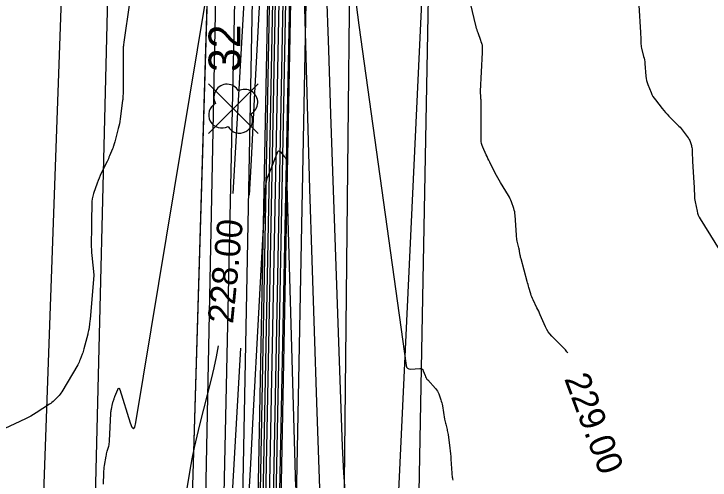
# Model space of a CAD drawing. Extents: x -534410 to -534262, y -1190162 to -1189584.
# Drawn here: x -534375.88 to -534348.61, y -1189725.88 to -1189707.6 of the extents above; entities that cross this region are included whole.
import ezdxf

# ---------------------------------------------------------------- set-up
doc = ezdxf.new("R2010")
doc.units = 0
for name, color, linetype in [('30', 7, 'Continuous'), ('31', 7, 'Continuous'), ('40', 7, 'Continuous'), ('_linie', 7, 'Continuous'), ('_N_osa', 7, 'Continuous'), ('_N_tenká', 7, 'Continuous'), ('_N_tenká_velmi', 7, 'Continuous'), ('_přístup', 7, 'Continuous'), ('_tenka', 7, 'Continuous'), ('Default', 7, 'Continuous'), ('Hranice parcel', 7, 'Continuous')]:
    doc.layers.add(name, color=color, linetype=linetype)

msp = doc.modelspace()

# ---------------------------------------------------------------- linework, layer by layer
at = {"layer": '30'}
for points in [[(-534365.702, -1189685.448), (-534366.553, -1189701.366), (-534366.64, -1189702.98), (-534366.729, -1189704.594), (-534366.819, -1189706.208), (-534366.911, -1189707.822), (-534367.302, -1189714.644)], [(-534362.885, -1189726.642), (-534362.961, -1189725.602), (-534363.011, -1189724.559), (-534363.467, -1189711.528), (-534363.552, -1189709.008), (-534363.634, -1189706.488), (-534363.71, -1189703.968), (-534363.782, -1189701.447), (-534364.144, -1189688.321)], [(-534371.366, -1189707.267), (-534371.561, -1189708.625), (-534371.574, -1189708.713), (-534371.588, -1189708.81), (-534371.59, -1189708.827), (-534371.592, -1189708.845), (-534371.594, -1189708.862), (-534371.595, -1189708.88), (-534371.6, -1189708.95), (-534371.601, -1189708.967), (-534371.602, -1189708.985), (-534371.603, -1189709.003), (-534371.603, -1189709.02), (-534371.603, -1189710.669), (-534371.603, -1189710.686), (-534371.603, -1189710.704), (-534371.604, -1189710.722), (-534371.605, -1189710.739), (-534371.609, -1189710.814), (-534371.611, -1189710.844), (-534371.614, -1189710.875), (-534371.618, -1189710.937), (-534371.619, -1189710.952), (-534371.62, -1189710.968), (-534371.622, -1189710.983), (-534371.624, -1189710.998), (-534371.718, -1189711.722), (-534371.732, -1189711.816), (-534371.749, -1189711.91), (-534371.769, -1189712.003), (-534371.792, -1189712.095), (-534371.934, -1189712.623), (-534371.954, -1189712.697), (-534371.98, -1189712.795), (-534371.987, -1189712.82), (-534371.995, -1189712.844), (-534372.004, -1189712.868), (-534372.013, -1189712.891), (-534372.133, -1189713.172), (-534372.157, -1189713.226), (-534372.181, -1189713.28), (-534372.206, -1189713.334), (-534372.232, -1189713.388), (-534372.457, -1189713.849), (-534372.501, -1189713.944), (-534372.543, -1189714.041), (-534372.582, -1189714.139), (-534372.618, -1189714.238), (-534372.758, -1189714.643), (-534372.788, -1189714.744), (-534372.81, -1189714.847), (-534372.824, -1189714.952), (-534372.83, -1189715.058), (-534372.839, -1189715.699), (-534372.84, -1189715.723), (-534372.84, -1189715.748), (-534372.84, -1189715.772), (-534372.84, -1189715.796), (-534372.84, -1189715.893), (-534372.84, -1189715.917), (-534372.84, -1189715.941), (-534372.84, -1189715.966), (-534372.841, -1189715.99), (-534372.85, -1189716.619), (-534372.85, -1189716.732), (-534372.846, -1189716.844), (-534372.839, -1189716.957), (-534372.829, -1189717.069), (-534372.747, -1189717.839), (-534372.747, -1189717.849), (-534372.747, -1189717.85), (-534372.9, -1189719.581), (-534372.905, -1189719.63), (-534372.91, -1189719.679), (-534372.916, -1189719.727), (-534372.923, -1189719.776), (-534372.952, -1189719.97), (-534372.959, -1189720.019), (-534372.968, -1189720.067), (-534372.979, -1189720.115), (-534372.99, -1189720.162), (-534373.136, -1189720.736), (-534373.151, -1189720.79), (-534373.167, -1189720.844), (-534373.185, -1189720.897), (-534373.204, -1189720.949), (-534373.285, -1189721.158), (-534373.306, -1189721.21), (-534373.329, -1189721.261), (-534373.354, -1189721.311), (-534373.382, -1189721.359), (-534374.008, -1189722.424), (-534374.038, -1189722.472), (-534374.072, -1189722.517), (-534374.107, -1189722.561), (-534374.146, -1189722.602), (-534374.307, -1189722.764), (-534374.348, -1189722.803), (-534374.391, -1189722.84), (-534374.435, -1189722.874), (-534374.482, -1189722.906), (-534375.005, -1189723.243), (-534375.109, -1189723.308), (-534375.215, -1189723.369), (-534375.323, -1189723.427), (-534375.433, -1189723.48), (-534377.082, -1189724.25)], [(-534354.184, -1189720.889), (-534354.22, -1189720.847), (-534354.283, -1189720.779), (-534354.348, -1189720.712), (-534354.818, -1189720.233), (-534354.892, -1189720.151), (-534354.957, -1189720.064), (-534355.013, -1189719.971), (-534355.061, -1189719.872), (-534355.263, -1189719.406), (-534355.295, -1189719.334), (-534355.327, -1189719.263), (-534355.36, -1189719.193), (-534355.394, -1189719.122), (-534355.545, -1189718.817), (-534355.572, -1189718.759), (-534355.596, -1189718.7), (-534355.617, -1189718.641), (-534355.637, -1189718.58), (-534355.708, -1189718.336), (-534355.725, -1189718.275), (-534355.743, -1189718.214), (-534355.76, -1189718.152), (-534355.777, -1189718.091), (-534356.019, -1189717.212), (-534356.028, -1189717.176), (-534356.037, -1189717.14), (-534356.045, -1189717.103), (-534356.052, -1189717.066), (-534356.077, -1189716.918), (-534356.084, -1189716.881), (-534356.091, -1189716.845), (-534356.098, -1189716.808), (-534356.106, -1189716.771), (-534356.166, -1189716.508), (-534356.178, -1189716.452), (-534356.187, -1189716.395), (-534356.194, -1189716.338), (-534356.199, -1189716.281), (-534356.248, -1189715.494), (-534356.255, -1189715.427), (-534356.266, -1189715.36), (-534356.282, -1189715.294), (-534356.302, -1189715.23), (-534356.392, -1189714.973), (-534356.416, -1189714.909), (-534356.443, -1189714.848), (-534356.474, -1189714.787), (-534356.508, -1189714.729), (-534356.822, -1189714.218), (-534356.877, -1189714.126), (-534356.93, -1189714.033), (-534356.981, -1189713.939), (-534357.03, -1189713.844), (-534357.246, -1189713.413), (-534357.282, -1189713.341), (-534357.317, -1189713.269), (-534357.351, -1189713.196), (-534357.384, -1189713.123), (-534357.517, -1189712.83), (-534357.545, -1189712.756), (-534357.566, -1189712.68), (-534357.578, -1189712.603), (-534357.583, -1189712.523), (-534357.583, -1189711.08), (-534357.583, -1189711.042), (-534357.584, -1189711.005), (-534357.586, -1189710.968), (-534357.588, -1189710.93), (-534357.599, -1189710.781), (-534357.602, -1189710.744), (-534357.603, -1189710.706), (-534357.603, -1189710.669), (-534357.602, -1189710.632), (-534357.531, -1189709.112), (-534357.53, -1189709.085), (-534357.529, -1189709.058), (-534357.528, -1189709.032), (-534357.528, -1189709.005), (-534357.525, -1189708.887), (-534357.526, -1189708.866), (-534357.528, -1189708.845), (-534357.533, -1189708.825), (-534357.539, -1189708.805), (-534357.569, -1189708.725), (-534357.576, -1189708.705), (-534357.584, -1189708.685), (-534357.591, -1189708.665), (-534357.598, -1189708.645), (-534357.703, -1189708.344), (-534357.723, -1189708.287), (-534357.74, -1189708.229), (-534357.757, -1189708.171), (-534357.772, -1189708.113), (-534358.002, -1189707.188)], [(-534366.691, -1189726.823), (-534366.604, -1189725.242), (-534366.519, -1189723.661), (-534366.03, -1189714.51), (-534366.014, -1189714.344), (-534365.985, -1189714.18), (-534365.944, -1189714.02), (-534365.889, -1189713.862), (-534365.562, -1189713.034), (-534365.539, -1189712.992), (-534365.511, -1189712.975), (-534365.479, -1189712.982), (-534365.443, -1189713.014), (-534365.291, -1189713.19), (-534365.258, -1189713.235), (-534365.233, -1189713.285), (-534365.218, -1189713.337), (-534365.212, -1189713.394), (-534364.91, -1189724.332), (-534364.858, -1189726.175)], [(-534367.885, -1189720.616), (-534367.961, -1189721.046), (-534368.052, -1189721.483), (-534368.156, -1189721.917), (-534368.612, -1189723.709), (-534368.72, -1189724.153), (-534368.819, -1189724.599), (-534368.908, -1189725.047), (-534368.987, -1189725.497), (-534370.447, -1189734.343)]]:
    msp.add_lwpolyline(points, dxfattribs=at)
at = {"layer": '31'}
for points in [[(-534366.657, -1189714.707), (-534366.581, -1189713.329), (-534366.452, -1189710.949), (-534365.716, -1189697.176), (-534365.693, -1189696.926), (-534365.65, -1189696.68), (-534365.587, -1189696.439), (-534365.504, -1189696.202), (-534364.963, -1189694.83), (-534364.955, -1189694.815), (-534364.945, -1189694.809), (-534364.934, -1189694.812), (-534364.922, -1189694.823), (-534364.868, -1189694.885), (-534364.857, -1189694.901), (-534364.848, -1189694.918), (-534364.843, -1189694.937), (-534364.841, -1189694.956), (-534364.38, -1189711.668), (-534364.3, -1189714.46), (-534364.216, -1189717.252), (-534364.126, -1189720.044), (-534364.031, -1189722.836), (-534363.168, -1189747.541)], [(-534362.529, -1189706.819), (-534362.375, -1189708.044), (-534360.52, -1189721.385), (-534360.501, -1189721.451), (-534360.466, -1189721.497), (-534360.414, -1189721.522), (-534360.345, -1189721.527), (-534359.986, -1189721.502), (-534359.939, -1189721.505), (-534359.9, -1189721.521), (-534359.87, -1189721.55), (-534359.848, -1189721.592), (-534359.778, -1189721.784), (-534359.759, -1189721.831), (-534359.735, -1189721.875), (-534359.707, -1189721.917), (-534359.674, -1189721.956), (-534359.366, -1189722.295), (-534359.327, -1189722.341), (-534359.294, -1189722.391), (-534359.266, -1189722.444), (-534359.242, -1189722.5), (-534359.16, -1189722.73), (-534359.141, -1189722.787), (-534359.124, -1189722.846), (-534359.11, -1189722.905), (-534359.099, -1189722.965), (-534359.012, -1189723.491), (-534359.003, -1189723.542), (-534358.993, -1189723.592), (-534358.981, -1189723.643), (-534358.969, -1189723.693), (-534358.917, -1189723.892), (-534358.905, -1189723.942), (-534358.894, -1189723.993), (-534358.885, -1189724.043), (-534358.877, -1189724.094), (-534358.806, -1189724.631), (-534358.793, -1189724.738), (-534358.781, -1189724.845), (-534358.771, -1189724.952), (-534358.763, -1189725.059), (-534358.71, -1189725.787), (-534358.709, -1189725.798), (-534358.708, -1189725.81), (-534358.706, -1189725.821), (-534358.703, -1189725.832), (-534358.693, -1189725.877), (-534358.691, -1189725.888)], [(-534372.378, -1189726.039), (-534372.362, -1189725.613), (-534372.358, -1189725.536), (-534372.351, -1189725.458), (-534372.342, -1189725.381), (-534372.33, -1189725.304), (-534372.268, -1189724.946), (-534372.259, -1189724.895), (-534372.248, -1189724.845), (-534372.237, -1189724.795), (-534372.223, -1189724.745), (-534372.168, -1189724.547), (-534372.156, -1189724.497), (-534372.146, -1189724.446), (-534372.139, -1189724.396), (-534372.135, -1189724.344), (-534372.082, -1189723.265), (-534372.079, -1189723.222), (-534372.075, -1189723.18), (-534372.069, -1189723.138), (-534372.062, -1189723.096), (-534372.023, -1189722.896), (-534372.018, -1189722.871), (-534372.011, -1189722.845), (-534372.004, -1189722.82), (-534371.995, -1189722.795), (-534371.96, -1189722.695), (-534371.951, -1189722.671), (-534371.941, -1189722.646), (-534371.932, -1189722.621), (-534371.922, -1189722.597), (-534371.812, -1189722.325), (-534371.791, -1189722.285), (-534371.771, -1189722.273), (-534371.752, -1189722.287), (-534371.734, -1189722.328), (-534371.327, -1189723.633), (-534371.258, -1189723.809), (-534371.197, -1189723.865), (-534371.144, -1189723.801), (-534371.1, -1189723.617), (-534368.388, -1189707.194)], [(-534351.402, -1189707.265), (-534351.34, -1189708.333), (-534351.337, -1189708.384), (-534351.334, -1189708.435), (-534351.332, -1189708.486), (-534351.331, -1189708.537), (-534351.325, -1189708.742), (-534351.322, -1189708.793), (-534351.316, -1189708.844), (-534351.308, -1189708.894), (-534351.297, -1189708.944), (-534351.216, -1189709.267), (-534351.199, -1189709.337), (-534351.186, -1189709.408), (-534351.176, -1189709.48), (-534351.169, -1189709.552), (-534351.129, -1189710.048), (-534351.119, -1189710.132), (-534351.103, -1189710.214), (-534351.081, -1189710.295), (-534351.052, -1189710.374), (-534350.926, -1189710.688), (-534350.892, -1189710.764), (-534350.852, -1189710.838), (-534350.807, -1189710.909), (-534350.757, -1189710.977), (-534350.49, -1189711.311), (-534350.427, -1189711.388), (-534350.362, -1189711.464), (-534350.295, -1189711.537), (-534350.225, -1189711.608), (-534349.838, -1189711.999), (-534349.791, -1189712.047), (-534349.747, -1189712.097), (-534349.704, -1189712.148), (-534349.663, -1189712.201), (-534349.473, -1189712.456), (-534349.449, -1189712.491), (-534349.429, -1189712.527), (-534349.411, -1189712.565), (-534349.397, -1189712.604), (-534349.347, -1189712.764), (-534349.336, -1189712.805), (-534349.328, -1189712.845), (-534349.322, -1189712.887), (-534349.319, -1189712.928), (-534349.311, -1189713.171), (-534349.309, -1189713.225), (-534349.307, -1189713.28), (-534349.304, -1189713.334), (-534349.301, -1189713.389), (-534349.249, -1189714.217), (-534349.245, -1189714.279), (-534349.242, -1189714.342), (-534349.239, -1189714.405), (-534349.237, -1189714.468), (-534349.229, -1189714.719), (-534349.226, -1189714.782), (-534349.22, -1189714.844), (-534349.211, -1189714.906), (-534349.2, -1189714.968), (-534349.125, -1189715.334), (-534349.104, -1189715.414), (-534349.078, -1189715.491), (-534349.044, -1189715.566), (-534349.003, -1189715.638), (-534347.853, -1189717.495)], [(-534367.841, -1189735.505), (-534366.993, -1189720.703)]]:
    msp.add_lwpolyline(points, dxfattribs=at)
at = {"layer": '_linie'}
for points in [[(-534366.12, -1189620.81), (-534364.52, -1189627.2), (-534365.69, -1189653.8), (-534366.76, -1189684.81), (-534368.14, -1189748.73), (-534368.38, -1189779.14), (-534368.65, -1189820.64), (-534368.59, -1189847.58), (-534367.2, -1189913.8)], [(-534363.12, -1189621.02), (-534362.79, -1189621.58), (-534361.82, -1189627.79), (-534363.46, -1189653.55), (-534365.47, -1189684.77), (-534366.65, -1189748.83), (-534366.75, -1189779.47), (-534366.9, -1189820.47), (-534366.95, -1189846.72), (-534366.338, -1189888.804), (-534363.85, -1189911.95), (-534357.07, -1189929.19), (-534352.334, -1189940.856)], [(-534359.03, -1189621.26), (-534359.41, -1189621.83), (-534360.84, -1189627.76), (-534362.92, -1189653.56), (-534364.64, -1189685), (-534365.94, -1189748.9), (-534366.02, -1189779.52), (-534366.03, -1189820.5), (-534366.48, -1189846.73), (-534365.511, -1189888.873), (-534362.72, -1189912.12), (-534356.62, -1189928.64), (-534351.589, -1189940.594)]]:
    msp.add_lwpolyline(points, dxfattribs=at)
at = {"layer": '_N_osa'}
msp.add_lwpolyline([(-534351.95, -1189940.722), (-534356.845, -1189928.915), (-534363.285, -1189912.035), (-534365.925, -1189888.838), (-534366.715, -1189846.725), (-534366.465, -1189820.485), (-534366.385, -1189779.495), (-534366.295, -1189748.865), (-534365.055, -1189684.885), (-534363.19, -1189653.555), (-534361.333, -1189627.822)], dxfattribs=at)
at = {"layer": '_N_tenká'}
for points in [[(-534352.92, -1189941.124), (-534357.821, -1189929.303), (-534364.313, -1189912.285), (-534366.973, -1189888.908), (-534367.765, -1189846.73), (-534367.515, -1189820.479), (-534367.435, -1189779.492), (-534367.345, -1189748.853), (-534366.104, -1189684.844), (-534364.238, -1189653.486), (-534362.424, -1189628.352), (-534361.782, -1189627.792)], [(-534350.98, -1189940.319), (-534355.869, -1189928.527), (-534362.257, -1189911.785), (-534364.876, -1189888.769), (-534365.665, -1189846.72), (-534365.415, -1189820.491), (-534365.335, -1189779.498), (-534365.245, -1189748.877), (-534364.006, -1189684.926), (-534362.142, -1189653.624), (-534360.329, -1189628.488), (-534360.884, -1189627.851)]]:
    msp.add_lwpolyline(points, dxfattribs=at)
at = {"layer": '_N_tenká_velmi'}
for points in [[(-534352.366, -1189940.894), (-534357.263, -1189929.081), (-534363.726, -1189912.142), (-534366.374, -1189888.868), (-534367.165, -1189846.727), (-534366.915, -1189820.482), (-534366.835, -1189779.494), (-534366.745, -1189748.86), (-534365.505, -1189684.867), (-534363.639, -1189653.525), (-534361.782, -1189627.792)], [(-534352.181, -1189940.817), (-534357.077, -1189929.007), (-534363.53, -1189912.095), (-534366.174, -1189888.855), (-534366.965, -1189846.726), (-534366.715, -1189820.484), (-534366.635, -1189779.494), (-534366.545, -1189748.862), (-534365.305, -1189684.875), (-534363.439, -1189653.539), (-534361.583, -1189627.805)], [(-534352.089, -1189940.779), (-534356.984, -1189928.97), (-534363.432, -1189912.071), (-534366.074, -1189888.848), (-534366.865, -1189846.726), (-534366.615, -1189820.484), (-534366.535, -1189779.495), (-534366.445, -1189748.863), (-534365.205, -1189684.879), (-534363.34, -1189653.545), (-534361.483, -1189627.812)], [(-534351.812, -1189940.664), (-534356.706, -1189928.86), (-534363.138, -1189911.999), (-534365.775, -1189888.828), (-534366.565, -1189846.724), (-534366.315, -1189820.486), (-534366.235, -1189779.495), (-534366.145, -1189748.867), (-534364.905, -1189684.891), (-534363.04, -1189653.565), (-534361.184, -1189627.831)], [(-534351.719, -1189940.626), (-534356.613, -1189928.823), (-534363.04, -1189911.975), (-534365.675, -1189888.822), (-534366.465, -1189846.724), (-534366.215, -1189820.486), (-534366.135, -1189779.496), (-534366.045, -1189748.868), (-534364.805, -1189684.895), (-534362.941, -1189653.571), (-534361.084, -1189627.838)], [(-534351.534, -1189940.549), (-534356.427, -1189928.749), (-534362.844, -1189911.928), (-534365.475, -1189888.808), (-534366.265, -1189846.723), (-534366.015, -1189820.488), (-534365.935, -1189779.496), (-534365.845, -1189748.87), (-534364.605, -1189684.903), (-534362.741, -1189653.585), (-534360.884, -1189627.851)]]:
    msp.add_lwpolyline(points, dxfattribs=at)
at = {"layer": '_přístup'}
for p, q in [((-534366.317, -1189712.293), (-534368.263, -1189710.347)), ((-534368.263, -1189712.293), (-534366.317, -1189710.347))]:
    msp.add_line(p, q, dxfattribs=at)
msp.add_circle((-534367.29, -1189711.32), 0.000512, dxfattribs=at)
for centre, start, end in [((-534367.535, -1189710.871), 28.6209, 208.6209), ((-534366.841, -1189711.075), 298.6209, 118.6209), ((-534367.739, -1189711.565), 118.6209, 298.6209), ((-534367.045, -1189711.769), 208.6209, 28.6209)]:
    msp.add_arc(centre, 0.512, start, end, dxfattribs=at)
at = {"layer": '_tenka'}
for points in [[(-534349.13, -1189939.73), (-534354.63, -1189926.96), (-534362.03, -1189907.65), (-534364.521, -1189888.74), (-534364.47, -1189846.64), (-534364.29, -1189820.63), (-534364.22, -1189780.69), (-534363.18, -1189749.38), (-534362.5, -1189685.39), (-534360.27, -1189651.6), (-534357.03, -1189627.34), (-534354.77, -1189620.37)], [(-534366.12, -1189620.81), (-534364.52, -1189627.2), (-534365.69, -1189653.8), (-534366.76, -1189684.81), (-534368.14, -1189748.73), (-534368.38, -1189779.14), (-534368.65, -1189820.64), (-534368.59, -1189847.58), (-534367.2, -1189913.8)], [(-534366.12, -1189620.81), (-534364.52, -1189627.2), (-534365.69, -1189653.8), (-534366.76, -1189684.81), (-534368.14, -1189748.73), (-534368.38, -1189779.14), (-534368.65, -1189820.64), (-534368.59, -1189847.58), (-534367.2, -1189913.8)], [(-534363.12, -1189621.02), (-534362.79, -1189621.58), (-534361.82, -1189627.79), (-534363.46, -1189653.55), (-534365.47, -1189684.77), (-534366.65, -1189748.83), (-534366.75, -1189779.47), (-534366.9, -1189820.47), (-534366.95, -1189846.72), (-534366.338, -1189888.804), (-534363.85, -1189911.95), (-534357.07, -1189929.19), (-534352.334, -1189940.856)], [(-534363.12, -1189621.02), (-534362.79, -1189621.58), (-534361.82, -1189627.79), (-534363.46, -1189653.55), (-534365.47, -1189684.77), (-534366.65, -1189748.83), (-534366.75, -1189779.47), (-534366.9, -1189820.47), (-534366.95, -1189846.72), (-534366.338, -1189888.804), (-534363.85, -1189911.95), (-534357.07, -1189929.19), (-534352.334, -1189940.856)], [(-534359.03, -1189621.26), (-534359.41, -1189621.83), (-534360.84, -1189627.76), (-534362.92, -1189653.56), (-534364.64, -1189685), (-534365.94, -1189748.9), (-534366.02, -1189779.52), (-534366.03, -1189820.5), (-534366.48, -1189846.73), (-534365.511, -1189888.873), (-534362.72, -1189912.12), (-534356.62, -1189928.64), (-534351.589, -1189940.594)], [(-534359.03, -1189621.26), (-534359.41, -1189621.83), (-534360.84, -1189627.76), (-534362.92, -1189653.56), (-534364.64, -1189685), (-534365.94, -1189748.9), (-534366.02, -1189779.52), (-534366.03, -1189820.5), (-534366.48, -1189846.73), (-534365.511, -1189888.873), (-534362.72, -1189912.12), (-534356.62, -1189928.64), (-534351.589, -1189940.594)], [(-534368.65, -1189626.81), (-534368.65, -1189626.81), (-534367.31, -1189654.04), (-534367.67, -1189685.23), (-534369.56, -1189748.93), (-534369.48, -1189778.6), (-534369.45, -1189820.62), (-534369.45, -1189847.87), (-534371.206, -1189896.071), (-534372.39, -1189914.47)]]:
    msp.add_lwpolyline(points, dxfattribs=at)
at = {"layer": 'Default'}
msp.add_line((-534367.67, -1189685.23), (-534369.56, -1189748.93), dxfattribs=at)
msp.add_lwpolyline([(-534349.13, -1189939.73), (-534354.63, -1189926.96), (-534362.03, -1189907.65), (-534364.521, -1189888.74), (-534364.47, -1189846.64), (-534364.29, -1189820.63), (-534364.22, -1189780.69), (-534363.18, -1189749.38), (-534362.5, -1189685.39), (-534360.27, -1189651.6), (-534357.03, -1189627.34), (-534354.77, -1189620.37)], dxfattribs=at)
at = {"layer": 'Hranice parcel'}
for p, q in [((-534371.04, -1189658.4), (-534373.49, -1189759.21)), ((-534369.14, -1189764.19), (-534367.77, -1189697.34))]:
    msp.add_line(p, q, dxfattribs=at)
for points in [[(-534373.49, -1189759.21), (-534375.27, -1189742.09), (-534373.87, -1189702.99), (-534373.87, -1189662.03), (-534374.42, -1189646.7)], [(-534359.48, -1189697.97), (-534362.6, -1189764.35), (-534362.34, -1189901.56)], [(-534359.48, -1189697.97), (-534360.42, -1189747.8), (-534359.17, -1189788.69), (-534356.86, -1189843.2), (-534358.53, -1189915.98)]]:
    msp.add_lwpolyline(points, dxfattribs=at)

# ---------------------------------------------------------------- texts
at = {"layer": '40'}
for s, rotation, p in [('228.00', 84.4269, (-534367.3, -1189719.771)), ('229.00', 290.4514, (-534354.336, -1189721.904))]:
    msp.add_text(s, height=1, rotation=rotation, dxfattribs=at).set_placement(p)
at = {"layer": '_přístup'}
msp.add_text('32', height=1.25, rotation=90, dxfattribs=at).set_placement((-534367.007, -1189709.88))

doc.saveas('drawing.dxf')
